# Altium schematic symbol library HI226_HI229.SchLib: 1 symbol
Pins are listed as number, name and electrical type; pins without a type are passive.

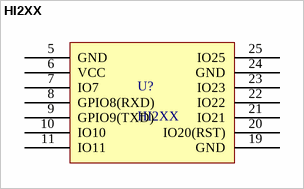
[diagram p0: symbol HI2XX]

## HI2XX
designator U?
footprint HI2XX_PLCC28 (Footprint not found)
pins: 5 GND, 6 VCC, 7 IO7, 8 GPIO8(RXD), 9 GPIO9(TXD), 10 IO10, 11 IO11, 19 GND, 20 IO20(RST), 21 IO21, 22 IO22, 23 IO23, 24 GND, 25 IO25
